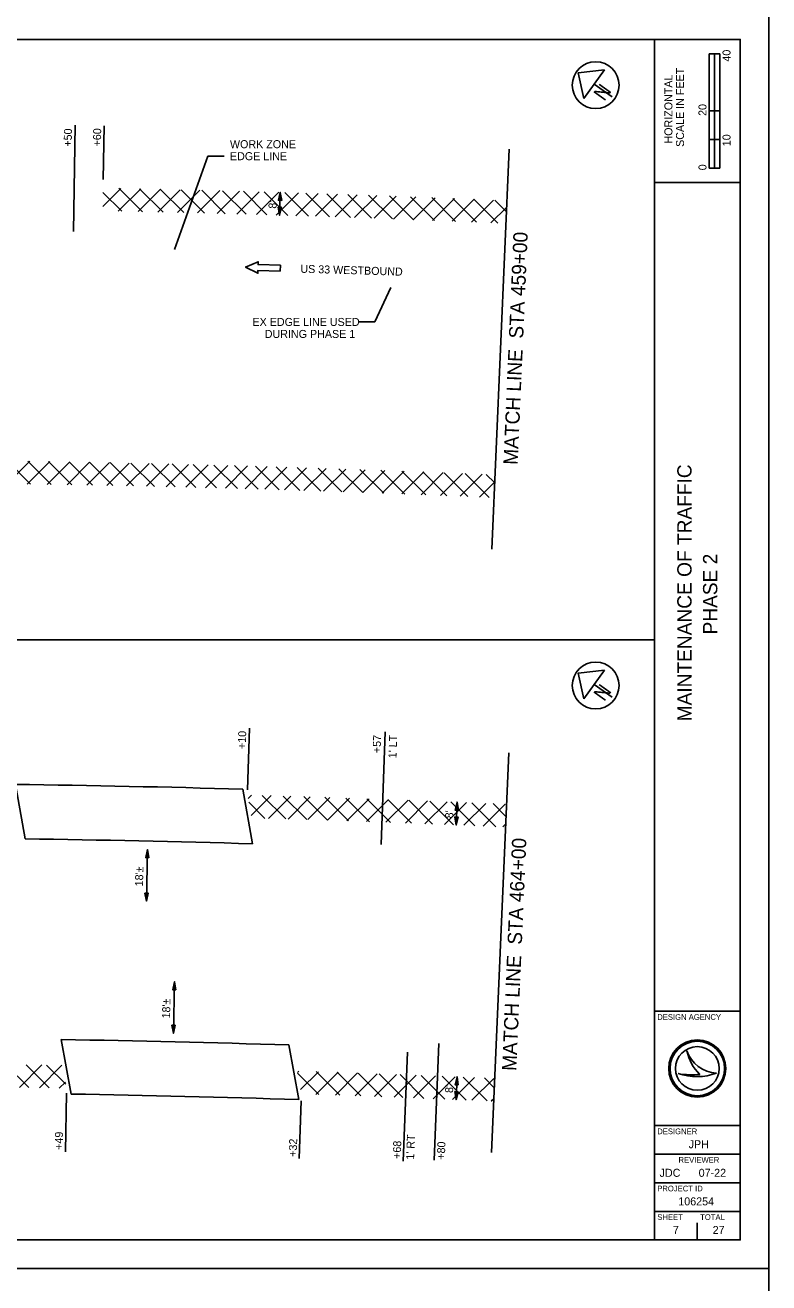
# Model space of a CAD drawing. Extents: x 0 to 5770, y -1320 to 440.
# Drawn here: x 420.1 to 680, y -885 to -445 of the extents above; entities that cross this region are included whole.
import ezdxf

# ---------------------------------------------------------------- set-up
doc = ezdxf.new("R2010")
doc.units = 0
for name, color, linetype in [('_CIVIL_CONSTRUCTION', 7, 'Continuous'), ('GE_P_Alignment', 7, 'Continuous'), ('GE_P_Alignment_100_Bearings', 7, 'Continuous'), ('GE_P_Alignment_100_Cardinal_Points', 7, 'Continuous'), ('GE_P_Alignment_100_Curve_Data', 7, 'Continuous'), ('GE_P_Alignment_100_Distances', 7, 'Continuous'), ('GE_P_Alignment_100_Stations', 7, 'Continuous'), ('HY_X_Water_Edge', 7, 'Continuous'), ('PM_X_Lane_Line', 7, 'Continuous')]:
    doc.layers.add(name, color=color, linetype=linetype)

msp = doc.modelspace()

# ---------------------------------------------------------------- linework, layer by layer
at = {"layer": '_CIVIL_CONSTRUCTION'}
for points in [[(0, -880), (680, -880), (680, -440), (0, -440)], [(0, -1320), (680, -1320), (680, -880), (0, -880)]]:
    msp.add_lwpolyline(points, close=True, dxfattribs=at)
at = {"layer": 'GE_P_Alignment'}
for p, q in [((640, -870), (640, -450)), ((640, -500), (670, -500)), ((640, -790), (670, -790)), ((640, -830), (670, -830)), ((640, -840), (670, -840)), ((640, -850), (670, -850)), ((640, -860), (670, -860))]:
    msp.add_line(p, q, dxfattribs=at)
msp.add_lwpolyline([(30, -450), (670, -450), (670, -870), (30, -870)], close=True, dxfattribs=at)
at = {"layer": 'GE_P_Alignment_100_Bearings'}
for p, q in [((659.13, -495), (659.13, -455)), ((662.88, -455), (659.13, -455)), ((659.13, -475), (659.13, -455)), ((659.13, -455), (661, -455)), ((661, -455), (661.02, -455)), ((661.02, -455), (661.02, -475)), ((662.88, -455), (662.88, -495)), ((661.02, -475), (659.13, -475)), ((662.87, -475), (661, -475)), ((661, -475), (661, -485)), ((662.87, -485), (662.87, -475)), ((661, -485), (659.13, -485)), ((659.13, -485), (659.13, -495)), ((661, -495), (661, -485)), ((661, -485), (662.87, -485)), ((662.88, -495), (659.13, -495)), ((659.13, -495), (661, -495)), ((651.35, -803.81), (651.35, -803.81)), ((648.34, -811.81), (648.34, -811.81)), ((655, -810), (655, -810)), ((661.75, -811.63), (661.75, -811.63)), ((647.5, -866.5), (647.5, -866.5)), ((655, -870), (655, -864))]:
    msp.add_line(p, q, dxfattribs=at)
for radius in [10, 9.54, 9.54, 7.64]:
    msp.add_circle((655, -810), radius, dxfattribs=at)
for centre, radius, start, end in [((662.32, -800.05), 11.6, 198.9257, 198.9319), ((666.93, -800.6), 15.91, 191.6379, 191.6421), ((662.32, -800.05), 11.6, 198.9319, 267.1657), ((666.93, -800.6), 15.91, 191.6421, 226.0947), ((654.79, -792.6), 20.26, 251.4576, 290.0832), ((652.96, -786.91), 25.32, 259.4964, 259.4995), ((654.79, -792.6), 20.26, 251.4527, 251.4576), ((652.96, -786.91), 25.32, 259.4995, 276.6672)]:
    msp.add_arc(centre, radius, start, end, dxfattribs=at)
at = {"layer": 'GE_P_Alignment_100_Cardinal_Points'}
for p, q in [((622.52, -460.63), (613.39, -461.66)), ((613.39, -461.66), (615.36, -470.63)), ((615.36, -470.63), (622.52, -460.63)), ((618.94, -465.63), (625.23, -470.13)), ((30, -660), (640, -660)), ((622.52, -670.63), (613.39, -671.66)), ((613.39, -671.66), (615.36, -680.63)), ((615.36, -680.63), (622.52, -670.63)), ((618.94, -675.63), (625.23, -680.13))]:
    msp.add_line(p, q, dxfattribs=at)
for centre in [(619.47, -466.01), (619.47, -676.01)]:
    msp.add_circle(centre, 8.2, dxfattribs=at)
at = {"layer": 'GE_P_Alignment_100_Curve_Data'}
for p, q in [((436.93, -517.21), (437.58, -480.03)), ((447.34, -499.02), (447.7, -480.2)), ((483.94, -490.84), (472.28, -523.52)), ((489.64, -490.84), (483.94, -490.84)), ((583.16, -628.3), (589.27, -488.43)), ((509.01, -511.49), (509.25, -503.5)), ((542.23, -548.83), (547.85, -536.8)), ((542.23, -548.83), (536.53, -548.83)), ((497.83, -712.56), (498.43, -690.94)), ((544.51, -731.61), (545.94, -692.19)), ((583.02, -839.45), (589.13, -699.58)), ((570.74, -724.83), (571.01, -716.83)), ((462.81, -733.45), (462.42, -751.45)), ((472.29, -779.68), (471.86, -797.68)), ((553.7, -804.29), (552.24, -842.47)), ((563.04, -842.05), (564.68, -801.27)), ((570.68, -820.91), (571.01, -812.92)), ((434.46, -818.65), (434.1, -839.18)), ((516.52, -821.3), (515.88, -841.53))]:
    msp.add_line(p, q, dxfattribs=at)
msp.add_lwpolyline([(509.23, -531.01), (501.43, -530.78), (501.4, -531.81), (497.12, -529.66), (501.52, -527.76), (501.49, -528.78), (509.29, -529.01)], close=True, dxfattribs=at)
at = {"layer": 'GE_P_Alignment_100_Distances'}
for points in [[(509.73, -506.31), (508.61, -506.28), (509.25, -503.5)], [(508.53, -508.68), (509.65, -508.71), (509.01, -511.49)], [(571.48, -719.65), (570.36, -719.61), (571.01, -716.83)], [(570.27, -722.01), (571.39, -722.05), (570.74, -724.83)], [(463.31, -736.27), (462.19, -736.24), (462.81, -733.45)], [(461.92, -748.64), (463.04, -748.66), (462.42, -751.45)], [(472.78, -782.5), (471.66, -782.47), (472.29, -779.68)], [(471.36, -794.87), (472.48, -794.89), (471.86, -797.68)], [(571.45, -815.74), (570.34, -815.69), (571.01, -812.92)], [(570.24, -818.09), (571.36, -818.13), (570.68, -820.91)]]:
    msp.add_lwpolyline(points, close=True, dxfattribs=at)
at = {"layer": 'GE_P_Alignment_100_Stations'}
for p, q in [((453.51, -502.1), (447.16, -508.45)), ((447.26, -503.56), (453.8, -510.11)), ((460.44, -502.24), (452.6, -510.08)), ((452.85, -502.08), (461.02, -510.26)), ((467.36, -502.4), (459.53, -510.23)), ((460.07, -502.23), (468.25, -510.42)), ((474.27, -502.56), (466.45, -510.38)), ((467.3, -502.39), (475.49, -510.59)), ((481.17, -502.73), (473.36, -510.54)), ((474.54, -502.56), (482.74, -510.77)), ((488.07, -502.9), (480.26, -510.71)), ((481.79, -502.74), (490, -510.96)), ((494.95, -503.09), (487.16, -510.88)), ((489.05, -502.93), (497.27, -511.15)), ((501.83, -503.28), (494.04, -511.07)), ((496.32, -503.12), (504.55, -511.36)), ((508.7, -503.48), (500.92, -511.26)), ((503.59, -503.33), (511.84, -511.58)), ((515.56, -503.69), (507.79, -511.46)), ((510.88, -503.55), (519.14, -511.81)), ((522.42, -503.91), (514.66, -511.67)), ((518.18, -503.77), (526.45, -512.04)), ((529.26, -504.13), (521.51, -511.88)), ((525.48, -504.01), (533.76, -512.29)), ((536.1, -504.36), (528.36, -512.11)), ((532.8, -504.25), (541.09, -512.54)), ((542.93, -504.6), (535.2, -512.34)), ((540.12, -504.5), (548.43, -512.81)), ((549.76, -504.85), (542.03, -512.58)), ((547.46, -504.77), (555.77, -513.08)), ((556.57, -505.11), (548.85, -512.82)), ((554.8, -505.04), (563.13, -513.37)), ((563.38, -505.37), (555.67, -513.08)), ((562.15, -505.32), (570.49, -513.66)), ((570.18, -505.64), (562.48, -513.34)), ((576.97, -505.92), (569.28, -513.61)), ((569.52, -505.62), (577.87, -513.97)), ((576.89, -505.92), (585.25, -514.28)), ((583.75, -506.21), (576.07, -513.89)), ((588.39, -508.65), (582.86, -514.18)), ((584.27, -506.23), (588.31, -510.27)), ((421.7, -597.55), (413.81, -605.44)), ((413.85, -597.44), (421.97, -605.56)), ((428.66, -597.66), (420.78, -605.54)), ((421.03, -597.54), (429.15, -605.67)), ((435.62, -597.78), (427.75, -605.65)), ((428.21, -597.65), (436.35, -605.79)), ((442.56, -597.9), (434.7, -605.76)), ((435.4, -597.77), (443.55, -605.92)), ((449.5, -598.04), (441.65, -605.89)), ((442.6, -597.9), (450.76, -606.06)), ((456.43, -598.18), (448.59, -606.02)), ((449.81, -598.04), (457.98, -606.21)), ((463.35, -598.33), (455.52, -606.16)), ((457.03, -598.19), (465.21, -606.37)), ((464.26, -598.35), (472.45, -606.54)), ((470.26, -598.49), (462.44, -606.31)), ((477.17, -598.66), (469.35, -606.47)), ((471.5, -598.52), (479.7, -606.72)), ((484.06, -598.83), (476.26, -606.64)), ((478.75, -598.69), (486.96, -606.91)), ((490.95, -599.01), (483.15, -606.81)), ((486.01, -598.88), (494.23, -607.11)), ((497.83, -599.2), (490.04, -606.99)), ((493.27, -599.08), (501.51, -607.31)), ((504.7, -599.4), (496.92, -607.18)), ((500.55, -599.28), (508.8, -607.53)), ((511.56, -599.61), (503.8, -607.38)), ((507.84, -599.5), (516.1, -607.76)), ((518.42, -599.83), (510.66, -607.59)), ((515.13, -599.72), (523.4, -607.99)), ((525.27, -600.05), (517.52, -607.8)), ((522.44, -599.96), (530.72, -608.24)), ((532.11, -600.28), (524.36, -608.03)), ((529.75, -600.2), (538.05, -608.5)), ((538.94, -600.52), (531.2, -608.26)), ((537.08, -600.46), (545.38, -608.76)), ((545.76, -600.77), (538.04, -608.5)), ((544.41, -600.72), (552.73, -609.04)), ((552.58, -601.03), (544.86, -608.74)), ((559.39, -601.29), (551.68, -609)), ((551.76, -600.99), (560.09, -609.32)), ((566.19, -601.56), (558.49, -609.26)), ((559.11, -601.28), (567.45, -609.62)), ((572.98, -601.84), (565.29, -609.53)), ((566.48, -601.57), (574.83, -609.92)), ((579.76, -602.13), (572.08, -609.81)), ((573.85, -601.87), (582.22, -610.24)), ((581.24, -602.19), (584.17, -605.12)), ((584.19, -604.77), (578.86, -610.09)), ((499.13, -714.36), (497.99, -715.5)), ((498.23, -716.84), (503.89, -722.5)), ((506.01, -714.56), (499.07, -721.5)), ((502.93, -714.47), (511.18, -722.72)), ((512.87, -714.76), (505.1, -722.53)), ((510.21, -714.68), (518.47, -722.94)), ((519.73, -714.98), (511.97, -722.74)), ((517.51, -714.91), (525.78, -723.18)), ((526.58, -715.2), (518.82, -722.95)), ((524.82, -715.14), (533.1, -723.42)), ((533.42, -715.43), (525.68, -723.17)), ((532.13, -715.38), (540.42, -723.68)), ((540.25, -715.67), (532.52, -723.4)), ((547.08, -715.91), (539.35, -723.64)), ((539.45, -715.64), (547.76, -723.94)), ((553.9, -716.16), (546.18, -723.88)), ((546.79, -715.9), (555.1, -724.22)), ((560.71, -716.42), (553, -724.14)), ((554.13, -716.17), (562.46, -724.5)), ((567.51, -716.69), (559.81, -724.4)), ((561.48, -716.46), (569.82, -724.79)), ((574.31, -716.97), (566.61, -724.66)), ((568.85, -716.75), (577.2, -725.1)), ((576.22, -717.05), (584.58, -725.41)), ((581.09, -717.25), (573.41, -724.94)), ((587.87, -717.54), (580.2, -725.22)), ((583.6, -717.36), (588.15, -721.91)), ((588.04, -724.44), (586.98, -725.51)), ((413.2, -808.58), (421.31, -816.7)), ((425.94, -808.77), (418.05, -816.65)), ((420.37, -808.69), (428.5, -816.81)), ((432.89, -808.89), (425.02, -816.76)), ((427.55, -808.8), (434.23, -815.48)), ((515.73, -810.9), (515.24, -811.39)), ((515.29, -811.69), (522.74, -819.13)), ((522.58, -811.12), (516.32, -817.38)), ((529.42, -811.35), (521.68, -819.09)), ((521.77, -811.09), (530.05, -819.37)), ((536.26, -811.58), (528.52, -819.32)), ((529.09, -811.34), (537.38, -819.63)), ((543.09, -811.83), (535.36, -819.56)), ((536.41, -811.59), (544.72, -819.89)), ((549.9, -812.08), (542.18, -819.8)), ((543.75, -811.85), (552.06, -820.17)), ((556.71, -812.34), (549, -820.05)), ((551.09, -812.13), (559.42, -820.45)), ((563.52, -812.61), (555.81, -820.31)), ((558.44, -812.41), (566.78, -820.75)), ((570.31, -812.89), (562.62, -820.58)), ((565.81, -812.7), (574.16, -821.05)), ((577.1, -813.17), (569.41, -820.86)), ((573.18, -813.01), (581.54, -821.37)), ((583.88, -813.46), (576.2, -821.14)), ((580.57, -813.32), (584.01, -816.77)), ((434.1, -814.75), (431.98, -816.87)), ((583.85, -820.57), (582.98, -821.43))]:
    msp.add_line(p, q, dxfattribs=at)
at = {"layer": 'HY_X_Water_Edge'}
for centre in [(619.47, -466.01), (619.47, -676.01)]:
    msp.add_circle(centre, 8.2, dxfattribs=at)
at = {"layer": 'PM_X_Lane_Line'}
for p, q in [((420.06, -729.67), (416.63, -710.62)), ((499.58, -731.38), (496.14, -712.28)), ((436.12, -818.94), (432.69, -799.88)), ((515.68, -820.9), (512.24, -801.79))]:
    msp.add_line(p, q, dxfattribs=at)
for radius, start, end in [(5783.58, 88.414909, 89.202697), (5764.58, 88.375505, 89.165995), (5694.58, 88.22801, 89.02863), (5675.58, 88.18734, 88.99075)]:
    msp.add_arc((336.16, -6493.64), radius, start, end, dxfattribs=at)

# ---------------------------------------------------------------- texts
at = {"layer": 'GE_P_Alignment_100_Bearings'}
for s, height, rotation, p in [('40', 2.8, 90, (666.61, -457.75)), ('SCALE IN FEET', 2.8, 90, (650.35, -487.59)), ('HORIZONTAL', 2.8, 90, (646.3, -486.42)), ('20', 2.8, 90, (658.21, -476.75)), ('10', 2.8, 90, (666.61, -487.35)), ('0', 2.8, 90, (658.21, -495.77)), ('MATCH LINE  STA 459+00', 5, 87.5, (592.2, -598.9)), ('MAINTENANCE OF TRAFFIC', 5, 90, (653, -688.55)), ('PHASE 2', 5, 90, (662, -658.17)), ('MATCH LINE  STA 464+00', 5, 87.5, (591.72, -810.93))]:
    msp.add_text(s, height=height, rotation=rotation, dxfattribs=at).set_placement(p)
for s, height, p in [('DESIGN AGENCY', 2, (641, -793)), ('DESIGNER', 2, (641, -833)), ('JPH', 2.8, (651.97, -837.9)), ('REVIEWER', 2, (648.44, -843)), ('JDC', 2.8, (641.82, -847.9)), ('07-22', 2.8, (655.48, -847.9)), ('PROJECT ID', 2, (641, -853)), ('106254', 2.8, (648.36, -857.9)), ('SHEET', 2, (641, -863)), ('TOTAL', 2, (656, -863)), ('7', 2.8, (646.48, -867.9)), ('27', 2.8, (660.37, -867.9))]:
    msp.add_text(s, height=height, dxfattribs=at).set_placement(p)
at = {"layer": 'GE_P_Alignment_100_Cardinal_Points'}
for p in [(622.44, -471.86), (622.44, -681.86)]:
    msp.add_text('N', height=5, rotation=54.4056, dxfattribs=at).set_placement(p)
at = {"layer": 'GE_P_Alignment_100_Curve_Data'}
for s, rotation, p in [('+50', 89, (436.32, -487.52)), ('+60', 88.9, (446.53, -487.45)), ("8'", 88.2857, (507.9, -509.23)), ('US 33 WESTBOUND', 358.3309, (516.22, -531.61)), ('+10', 88.3981, (497.18, -698.29)), ('+57', 87.929, (544.3, -699.72)), ("1' LT", 87.929, (549.82, -701.53)), ("8'", 88.0232, (569.64, -722.56)), ("18'±", 88.7404, (461.24, -746.31)), ("18'±", 88.6352, (470.69, -792.54)), ("8'", 87.6326, (569.6, -818.63)), ('+49', 89.0076, (433.2, -838.48)), ('+32', 88.1787, (514.96, -840.94)), ('+68', 87.8103, (551.3, -841.67)), ("1' RT", 87.8103, (555.99, -841.96)), ('+80', 87.7011, (566.73, -841.97))]:
    msp.add_text(s, height=2.8, rotation=rotation, dxfattribs=at).set_placement(p)
for s, p in [('WORK ZONE', (491.64, -488.04)), ('EDGE LINE', (491.64, -492.24)), ('EX EDGE LINE USED', (499.51, -550.23)), ('DURING PHASE 1', (503.81, -554.43))]:
    msp.add_text(s, height=2.8, dxfattribs=at).set_placement(p)

doc.saveas('drawing.dxf')
